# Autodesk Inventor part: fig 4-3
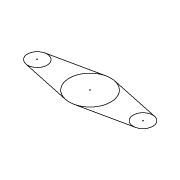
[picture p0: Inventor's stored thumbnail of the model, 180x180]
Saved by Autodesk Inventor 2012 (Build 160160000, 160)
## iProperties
Created: 2005-02
Part Number: fig 4-3
Document SubType Name: Modeling
Designer: CADCIM
Manufacturer: Standard
Standards Organization: Custom
Density: 1 g/cm^3
Material: Default
Author: CADCIM
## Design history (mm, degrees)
sketch "Sketch1"
  geometry: L1 (-33.874, 5.844)-(-2.722, 12.469); L2 (2.595, 12.472)-(33.871, 5.852); L3 (-33.884, -5.902)-(-2.745, -12.585); L4 (2.595, -12.592)-(33.871, -5.972); A1 r 12.81 centre (-0.057, -0.06) between (-2.722, 12.469) and (2.595, 12.472); A2 r 6.006 centre (-32.624, -0.03) between (-33.874, 5.844) and (-33.884, -5.902); A3 r 6.043 centre (32.619, -0.06) between (33.871, 5.852) and (33.871, -5.972)
  constraints: 8 end point, 8 point on circle, 8 tangent, 3 centre point, 1 other
